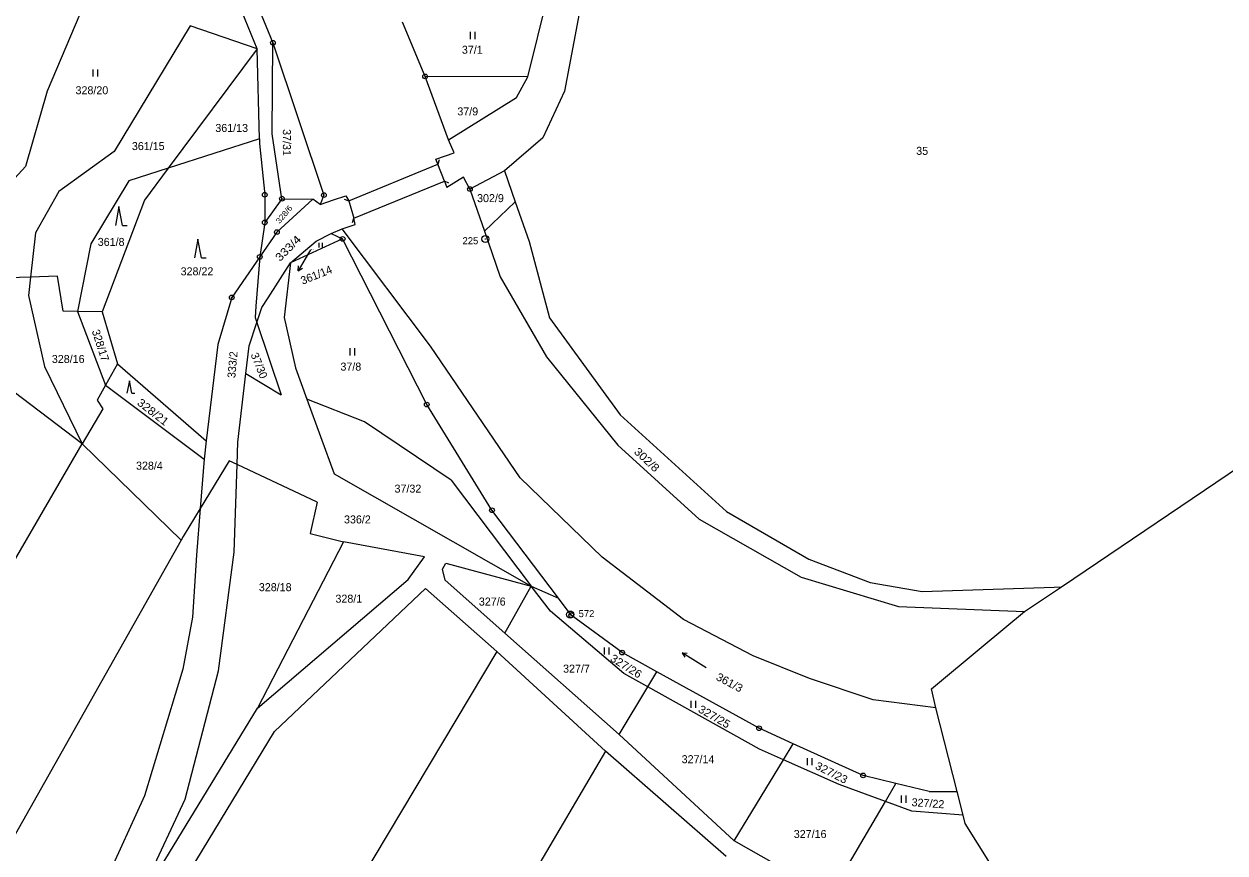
# Model space of a CAD drawing. Extents: x -645290 to -643454, y -1064771 to -1062356.
# Drawn here: x -644666.5 to -644411.4, y -1064149.2 to -1063973.1 of the extents above; entities that cross this region are included whole.
import ezdxf
from ezdxf.enums import TextEntityAlignment as Align

# ---------------------------------------------------------------- set-up
doc = ezdxf.new("R2010")
doc.units = 0
doc.header["$LTSCALE"] = 0.68
for name, color, linetype, lineweight in [('1', 7, 'Continuous', 25), ('3', 7, 'Continuous', 25), ('4', 7, 'Continuous', 13), ('7', 7, 'Continuous', 13), ('8', 7, 'Continuous', 25)]:
    doc.layers.add(name, color=color, linetype=linetype, lineweight=lineweight)
doc.layers.add('2', color=7, linetype='Continuous')

msp = doc.modelspace()

# ---------------------------------------------------------------- linework, layer by layer
at = {"layer": '1'}
for p, q in [((-644621.6, -1063957.55), (-644613.6, -1063977.09)), ((-644616.95, -1063978.39), (-644624.84, -1063958.87)), ((-644559.44, -1063984.36), (-644554.73, -1063965.42)), ((-644547.65, -1063966.35), (-644549.67, -1063976.91)), ((-644654.6, -1063971.04), (-644661.51, -1063987.36)), ((-644581.25, -1063984.25), (-644586.08, -1063972.72)), ((-644631.17, -1063973.52), (-644647.27, -1064000.18)), ((-644616.95, -1063978.39), (-644631.17, -1063973.52)), ((-644613.77, -1063996.44), (-644613.6, -1063977.09)), ((-644613.6, -1063977.09), (-644602.75, -1064009.47)), ((-644549.67, -1063976.91), (-644551.68, -1063987.36)), ((-644616.95, -1063978.39), (-644635.83, -1064003.74)), ((-644616.46, -1063997.53), (-644616.95, -1063978.39)), ((-644559.44, -1063984.36), (-644581.25, -1063984.25)), ((-644576.27, -1063997.73), (-644581.25, -1063984.25)), ((-644561.85, -1063988.75), (-644559.44, -1063984.36)), ((-644661.51, -1063987.36), (-644666.16, -1064003.4)), ((-644551.68, -1063987.36), (-644556.25, -1063997.28)), ((-644576.27, -1063997.73), (-644561.85, -1063988.75)), ((-644616.46, -1063997.53), (-644635.83, -1064003.74)), ((-644616.46, -1063997.53), (-644616.44, -1063998.48)), ((-644616.44, -1063998.48), (-644615.32, -1064009.4)), ((-644611.67, -1064010.23), (-644613.77, -1063996.44)), ((-644575.1, -1064000.47), (-644576.27, -1063997.73)), ((-644556.25, -1063997.28), (-644564.39, -1064004.34)), ((-644647.27, -1064000.18), (-644659.04, -1064008.73)), ((-644578.95, -1064001.85), (-644575.1, -1064000.47)), ((-644666.16, -1064003.4), (-644670.66, -1064008.32)), ((-644578.53, -1064002.93), (-644578.95, -1064001.85)), ((-644577.14, -1064006.51), (-644578.53, -1064002.93)), ((-644635.83, -1064003.74), (-644644.19, -1064006.42)), ((-644635.83, -1064003.74), (-644640.87, -1064010.51)), ((-644573.1, -1064005.65), (-644576.62, -1064007.88)), ((-644571.73, -1064008.18), (-644573.1, -1064005.65)), ((-644564.39, -1064004.34), (-644571.73, -1064008.18)), ((-644564.39, -1064004.34), (-644562.1, -1064010.87)), ((-644659.04, -1064008.73), (-644664.02, -1064017.46)), ((-644644.19, -1064006.42), (-644652.29, -1064019.8)), ((-644577.14, -1064006.51), (-644576.62, -1064007.88)), ((-644571.73, -1064008.18), (-644568.65, -1064017.15)), ((-644640.87, -1064010.51), (-644649.88, -1064034.3)), ((-644615.32, -1064009.4), (-644615.32, -1064015.29)), ((-644611.67, -1064010.23), (-644615.32, -1064015.29)), ((-644605.13, -1064010.36), (-644612.74, -1064017.34)), ((-644611.67, -1064010.23), (-644605.13, -1064010.36)), ((-644603.57, -1064011.46), (-644605.13, -1064010.36)), ((-644602.75, -1064009.47), (-644603.57, -1064011.46)), ((-644603.57, -1064011.46), (-644600.73, -1064010.49)), ((-644600.73, -1064010.49), (-644598.11, -1064009.61)), ((-644598.11, -1064009.61), (-644597.49, -1064010.68)), ((-644597.49, -1064010.68), (-644596.38, -1064014.34)), ((-644568.65, -1064017.15), (-644562.1, -1064010.87)), ((-644562.1, -1064010.87), (-644559.12, -1064019.33)), ((-644615.32, -1064015.29), (-644616.37, -1064022.59)), ((-644598.85, -1064016.67), (-644596.09, -1064015.71)), ((-644596.09, -1064015.71), (-644596.38, -1064014.34)), ((-644664.02, -1064017.46), (-644665.04, -1064026.88)), ((-644612.74, -1064017.34), (-644616.37, -1064022.59)), ((-644598.77, -1064018.77), (-644609.82, -1064023.89)), ((-644604.43, -1064019.27), (-644601.19, -1064017.65)), ((-644601.19, -1064017.65), (-644598.85, -1064016.67)), ((-644601.19, -1064017.65), (-644598.77, -1064018.77)), ((-644580.13, -1064041.56), (-644598.85, -1064016.67)), ((-644580.91, -1064053.97), (-644598.77, -1064018.77)), ((-644568.65, -1064017.15), (-644565.32, -1064026.84)), ((-644652.29, -1064019.8), (-644655.11, -1064034.23)), ((-644609.82, -1064023.89), (-644604.43, -1064019.27)), ((-644559.12, -1064019.33), (-644554.82, -1064035.56)), ((-644616.37, -1064022.59), (-644622.34, -1064031.2)), ((-644616.37, -1064022.59), (-644617.19, -1064033.09)), ((-644614.59, -1064031.29), (-644609.82, -1064023.89)), ((-644609.82, -1064023.89), (-644611.22, -1064035.44)), ((-644665.04, -1064026.88), (-644672.56, -1064027.12)), ((-644665.04, -1064026.88), (-644665.47, -1064030.8)), ((-644659.34, -1064026.7), (-644665.04, -1064026.88)), ((-644658.14, -1064034.16), (-644659.34, -1064026.7)), ((-644565.32, -1064026.84), (-644555.5, -1064043.84)), ((-644665.47, -1064030.8), (-644662.12, -1064045.9)), ((-644622.34, -1064031.2), (-644625.31, -1064041.18)), ((-644615.92, -1064033.36), (-644614.59, -1064031.29)), ((-644655.11, -1064034.23), (-644658.14, -1064034.16)), ((-644649.88, -1064034.3), (-644655.11, -1064034.23)), ((-644655.11, -1064034.23), (-644649.11, -1064049.86)), ((-644617.19, -1064033.09), (-644617.34, -1064035.5)), ((-644616.99, -1064036.55), (-644615.92, -1064033.36)), ((-644649.88, -1064034.3), (-644646.58, -1064045.29)), ((-644618.64, -1064041.47), (-644616.99, -1064036.55)), ((-644617.34, -1064035.5), (-644616.99, -1064036.55)), ((-644616.99, -1064036.55), (-644611.82, -1064051.92)), ((-644554.82, -1064035.56), (-644539.85, -1064056.15)), ((-644625.31, -1064041.18), (-644627.74, -1064061.65)), ((-644619.32, -1064047.34), (-644618.64, -1064041.47)), ((-644561.08, -1064069.56), (-644580.13, -1064041.56)), ((-644654.09, -1064062.28), (-644680.91, -1064041.96)), ((-644555.5, -1064043.84), (-644540.34, -1064062.59)), ((-644662.12, -1064045.9), (-644654.09, -1064062.28)), ((-644646.58, -1064045.29), (-644649.11, -1064049.86)), ((-644646.58, -1064045.29), (-644627.74, -1064061.65)), ((-644621.03, -1064061.97), (-644619.32, -1064047.34)), ((-644619.32, -1064047.34), (-644611.82, -1064051.92)), ((-644649.11, -1064049.86), (-644650.93, -1064053.03)), ((-644649.11, -1064049.86), (-644628.21, -1064065.59)), ((-644650.93, -1064053.03), (-644649.73, -1064054.86)), ((-644606.37, -1064052.81), (-644600.56, -1064068.66)), ((-644594.12, -1064057.65), (-644606.37, -1064052.81)), ((-644567.05, -1064076.43), (-644580.91, -1064053.97)), ((-644446.09, -1064092.67), (-644389.56, -1064054.44)), ((-644649.73, -1064054.86), (-644654.09, -1064062.28)), ((-644517.23, -1064076.68), (-644539.85, -1064056.15)), ((-644575.75, -1064070), (-644594.12, -1064057.65)), ((-644794.48, -1064303.81), (-644654.09, -1064062.28)), ((-644633.09, -1064082.79), (-644654.09, -1064062.28)), ((-644627.74, -1064061.65), (-644628.21, -1064065.59)), ((-644621.19, -1064066.68), (-644621.03, -1064061.97)), ((-644540.34, -1064062.59), (-644523.03, -1064078.34)), ((-644628.21, -1064065.59), (-644629.05, -1064076.08)), ((-644622.86, -1064065.89), (-644629.05, -1064076.08)), ((-644621.19, -1064066.68), (-644622.86, -1064065.89)), ((-644621.81, -1064085.36), (-644621.19, -1064066.68)), ((-644604.16, -1064074.72), (-644621.19, -1064066.68)), ((-644600.56, -1064068.66), (-644558.7, -1064092.57)), ((-644543.64, -1064086.36), (-644561.08, -1064069.56)), ((-644575.75, -1064070), (-644558.7, -1064092.57)), ((-644604.16, -1064074.72), (-644605.66, -1064081.34)), ((-644629.05, -1064076.08), (-644632.63, -1064081.97)), ((-644629.05, -1064076.08), (-644629.84, -1064085.97)), ((-644552.95, -1064095.09), (-644567.05, -1064076.43)), ((-644517.23, -1064076.68), (-644499.75, -1064086.83)), ((-644523.03, -1064078.34), (-644501.38, -1064090.61)), ((-644632.63, -1064081.97), (-644633.09, -1064082.79)), ((-644605.66, -1064081.34), (-644598.6, -1064083.1)), ((-644633.09, -1064082.79), (-644728.84, -1064252.56)), ((-644598.6, -1064083.1), (-644616.86, -1064118.44)), ((-644581.42, -1064086.34), (-644598.6, -1064083.1)), ((-644629.84, -1064085.97), (-644630.64, -1064099.14)), ((-644625.15, -1064110.54), (-644621.81, -1064085.36)), ((-644584.88, -1064091.13), (-644581.42, -1064086.34)), ((-644577.53, -1064088.92), (-644576.86, -1064087.65)), ((-644576.86, -1064087.65), (-644558.7, -1064092.57)), ((-644526.35, -1064099.66), (-644543.64, -1064086.36)), ((-644499.75, -1064086.83), (-644486.74, -1064091.8)), ((-644576.99, -1064091.31), (-644577.53, -1064088.92)), ((-644616.86, -1064118.44), (-644584.88, -1064091.13)), ((-644564.35, -1064102.54), (-644576.99, -1064091.31)), ((-644564.35, -1064102.54), (-644558.7, -1064092.57)), ((-644558.7, -1064092.57), (-644552.95, -1064095.09)), ((-644554.6, -1064097.87), (-644558.7, -1064092.57)), ((-644501.38, -1064090.61), (-644480.67, -1064096.9)), ((-644486.74, -1064091.8), (-644475.7, -1064093.7)), ((-644475.7, -1064093.7), (-644447.66, -1064092.77)), ((-644453.91, -1064097.96), (-644446.09, -1064092.67)), ((-644447.66, -1064092.77), (-644446.09, -1064092.67)), ((-644613.22, -1064123.4), (-644581.18, -1064093.06)), ((-644581.18, -1064093.06), (-644566.05, -1064106.42)), ((-644550.22, -1064098.7), (-644552.95, -1064095.09)), ((-644539.08, -1064111.13), (-644554.6, -1064097.87)), ((-644480.67, -1064096.9), (-644453.91, -1064097.96)), ((-644462.7, -1064105.25), (-644453.91, -1064097.96)), ((-644630.64, -1064099.14), (-644632.7, -1064110.17)), ((-644539.41, -1064106.66), (-644550.22, -1064098.7)), ((-644511.55, -1064107.35), (-644526.35, -1064099.66)), ((-644540.03, -1064124.08), (-644564.35, -1064102.54)), ((-644473.67, -1064114.35), (-644462.7, -1064105.25)), ((-644566.05, -1064106.42), (-644726.5, -1064375.38)), ((-644542.91, -1064127.64), (-644566.05, -1064106.42)), ((-644532.03, -1064110.74), (-644539.41, -1064106.66)), ((-644499.61, -1064112.14), (-644511.55, -1064107.35)), ((-644632.7, -1064110.17), (-644640.85, -1064137.12)), ((-644632.24, -1064137.78), (-644625.15, -1064110.54)), ((-644533.97, -1064113.97), (-644532.03, -1064110.74)), ((-644510.32, -1064122.73), (-644532.03, -1064110.74)), ((-644533.97, -1064113.97), (-644539.08, -1064111.13)), ((-644486.07, -1064116.73), (-644499.61, -1064112.14)), ((-644540.03, -1064124.08), (-644533.97, -1064113.97)), ((-644510.23, -1064127.16), (-644533.97, -1064113.97)), ((-644472.76, -1064118.41), (-644473.67, -1064114.35)), ((-644643.64, -1064162.33), (-644616.86, -1064118.44)), ((-644472.76, -1064118.41), (-644486.07, -1064116.73)), ((-644468.24, -1064136.2), (-644472.76, -1064118.41)), ((-644711.6, -1064285.03), (-644613.22, -1064123.4)), ((-644503.08, -1064126.02), (-644510.32, -1064122.73)), ((-644515.6, -1064146.63), (-644540.03, -1064124.08)), ((-644505.15, -1064129.43), (-644503.08, -1064126.02)), ((-644488.22, -1064132.77), (-644503.08, -1064126.02)), ((-644542.91, -1064127.64), (-644679.8, -1064359.5)), ((-644517.28, -1064150.01), (-644542.91, -1064127.64)), ((-644505.15, -1064129.43), (-644510.23, -1064127.16)), ((-644515.6, -1064146.63), (-644505.15, -1064129.43)), ((-644493.31, -1064134.72), (-644505.15, -1064129.43)), ((-644481.26, -1064134.46), (-644488.22, -1064132.77)), ((-644483.49, -1064138.28), (-644493.31, -1064134.72)), ((-644483.49, -1064138.28), (-644481.26, -1064134.46)), ((-644474.2, -1064136.18), (-644481.26, -1064134.46)), ((-644474.2, -1064136.18), (-644468.24, -1064136.2)), ((-644466.97, -1064141.18), (-644468.24, -1064136.2)), ((-644640.85, -1064137.12), (-644651.74, -1064160.97)), ((-644643.64, -1064162.33), (-644632.24, -1064137.78)), ((-644495.15, -1064158.24), (-644483.49, -1064138.28)), ((-644477.85, -1064140.32), (-644483.49, -1064138.28)), ((-644466.97, -1064141.18), (-644477.85, -1064140.32)), ((-644466.54, -1064142.99), (-644466.97, -1064141.18)), ((-644456.36, -1064159.09), (-644466.54, -1064142.99)), ((-644495.15, -1064158.24), (-644515.6, -1064146.63))]:
    msp.add_line(p, q, dxfattribs=at)
msp.add_lwpolyline([(-644611.22, -1064035.44), (-644608.82, -1064046.14), (-644606.37, -1064052.81)], dxfattribs=at)
at = {"layer": '3'}
for p, q in [((-644571.641, -1063976.31), (-644571.641, -1063974.81)), ((-644570.64, -1063976.31), (-644570.64, -1063974.81)), ((-644651.791, -1063984.28), (-644651.791, -1063982.78)), ((-644650.79, -1063984.28), (-644650.79, -1063982.78)), ((-644645.54, -1064015.9), (-644644.544, -1064015.9)), ((-644603.732, -1064020.61), (-644603.732, -1064019.605)), ((-644603.062, -1064020.61), (-644603.062, -1064019.605)), ((-644628.75, -1064022.8), (-644627.754, -1064022.8)), ((-644597.181, -1064043.52), (-644597.181, -1064042.02)), ((-644596.18, -1064043.52), (-644596.18, -1064042.02)), ((-644643.578, -1064051.58), (-644642.91, -1064051.58)), ((-644543.131, -1064107.09), (-644543.131, -1064105.59)), ((-644542.13, -1064107.09), (-644542.13, -1064105.59)), ((-644526.674, -1064106.694), (-644525.58, -1064106.786)), ((-644524.721, -1064118.42), (-644524.721, -1064116.92)), ((-644523.72, -1064118.42), (-644523.72, -1064116.92)), ((-644500.061, -1064130.59), (-644500.061, -1064129.09)), ((-644499.06, -1064130.59), (-644499.06, -1064129.09)), ((-644480.091, -1064138.56), (-644480.091, -1064137.06)), ((-644479.09, -1064138.56), (-644479.09, -1064137.06))]:
    msp.add_line(p, q, dxfattribs=at)
for points in [[(-644645.54, -1064015.9), (-644646.29, -1064011.9), (-644647.04, -1064015.9)], [(-644628.75, -1064022.8), (-644629.5, -1064018.8), (-644630.25, -1064022.8)], [(-644643.578, -1064051.58), (-644644.08, -1064048.9), (-644644.582, -1064051.58)], [(-644521.586, -1064109.873), (-644526.674, -1064106.694), (-644526.111, -1064107.637)]]:
    msp.add_lwpolyline(points, dxfattribs=at)
at = {"layer": '4'}
for p, q in [((-644597.49, -1064010.68), (-644578.53, -1064002.93)), ((-644578.237, -1064001.973), (-644578.529, -1064002.93)), ((-644596.38, -1064014.34), (-644577.14, -1064006.51)), ((-644576.249, -1064006.965), (-644577.14, -1064006.511)), ((-644598.417, -1064010.305), (-644597.49, -1064010.679)), ((-644596.69, -1064015.291), (-644596.381, -1064014.34))]:
    msp.add_line(p, q, dxfattribs=at)
at = {"layer": '7'}
msp.add_line((-644608.2, -1064025.579), (-644607.266, -1064024.962), dxfattribs=at)
msp.add_lwpolyline([(-644605.59, -1064021.09), (-644606.7, -1064022.98), (-644608.2, -1064025.579), (-644608.133, -1064024.461)], dxfattribs=at)
at = {"layer": '8'}
for centre, radius in [((-644613.6, -1063977.0899), 0.5), ((-644613.6, -1063977.0899), 0.0303), ((-644581.25, -1063984.2499), 0.5), ((-644581.25, -1063984.2499), 0.0303), ((-644571.73, -1064008.1799), 0.5), ((-644571.73, -1064008.1799), 0.0303), ((-644615.32, -1064009.3999), 0.5), ((-644615.32, -1064009.3999), 0.0303), ((-644611.67, -1064010.2299), 0.5), ((-644611.67, -1064010.2299), 0.0303), ((-644602.75, -1064009.4699), 0.5), ((-644602.75, -1064009.4699), 0.0303), ((-644615.32, -1064015.2899), 0.5), ((-644615.32, -1064015.2899), 0.0303), ((-644612.74, -1064017.3399), 0.5), ((-644612.74, -1064017.3399), 0.0303), ((-644598.77, -1064018.7699), 0.5), ((-644598.77, -1064018.7699), 0.0303), ((-644568.46, -1064018.7898), 0.75), ((-644568.46, -1064018.7898), 0.03), ((-644616.37, -1064022.5899), 0.5), ((-644616.37, -1064022.5899), 0.0303), ((-644622.34, -1064031.1999), 0.5), ((-644622.34, -1064031.1999), 0.0303), ((-644580.91, -1064053.9699), 0.5), ((-644580.91, -1064053.9699), 0.0303), ((-644567.05, -1064076.4299), 0.5), ((-644567.05, -1064076.4299), 0.0303), ((-644550.44, -1064098.5798), 0.75), ((-644550.22, -1064098.6999), 0.5), ((-644550.44, -1064098.5798), 0.03), ((-644550.22, -1064098.6999), 0.0303), ((-644539.41, -1064106.6599), 0.5), ((-644539.41, -1064106.6599), 0.0303), ((-644510.32, -1064122.7299), 0.5), ((-644510.32, -1064122.7299), 0.0303), ((-644488.22, -1064132.7699), 0.5), ((-644488.22, -1064132.7699), 0.0303)]:
    msp.add_circle(centre, radius, dxfattribs=at)

# ---------------------------------------------------------------- texts
at = {"layer": '2'}
for s, p in [('37/1', (-644571.229, -1063979.435)), ('37/9', (-644572.199, -1063992.535))]:
    msp.add_text(s, height=1.7, dxfattribs=at).set_placement(p, align=Align.CENTER)
for s, height, p in [('328/20', 1.7, (-644655.51, -1063988.045)), ('361/13', 1.7, (-644625.82, -1063996.054)), ('361/15', 1.7, (-644643.54, -1063999.905)), ('35', 1.7, (-644476.94, -1064000.915)), ('302/9', 1.7, (-644570.22, -1064010.965)), ('361/8', 1.7, (-644650.79, -1064020.265)), ('361/14', 0.2, (-644605.59, -1064021.14)), ('328/22', 1.7, (-644633.19, -1064026.515)), ('328/16', 1.7, (-644660.54, -1064045.135)), ('37/8', 1.7, (-644599.24, -1064046.755)), ('328/4', 1.7, (-644642.66, -1064067.804)), ('37/32', 1.7, (-644587.75, -1064072.675)), ('336/2', 1.7, (-644598.48, -1064079.225)), ('328/18', 1.7, (-644616.57, -1064093.615)), ('328/1', 1.7, (-644600.3, -1064096.064)), ('327/6', 1.7, (-644569.84, -1064096.675)), ('327/7', 1.7, (-644551.95, -1064110.925)), ('327/14', 1.7, (-644526.76, -1064130.165)), ('327/16', 1.7, (-644502.95, -1064146.054))]:
    msp.add_text(s, height=height, dxfattribs=at).set_placement(p)
for s, rotation, p in [('37/31', 270, (-644611.465, -1063995.45)), ('328/17', 288, (-644652.074, -1064038.361)), ('333/2', 85, (-644621.576, -1064048.407)), ('37/30', 292, (-644618.354, -1064043.359)), ('327/22', 356, (-644477.969, -1064139.273))]:
    msp.add_text(s, height=1.7, rotation=rotation, dxfattribs=at).set_placement(p)
for s, height, rotation, width, p in [('328/6', 1.2, 50, 1.1, (-644612.16, -1064015.642)), ('333/4', 1.7, 45, 1.15, (-644612.079, -1064023.68)), ('328/21', 1.7, 322, 1.1, (-644642.581, -1064053.874)), ('302/8', 1.7, 317, 1.1, (-644537.029, -1064064.18)), ('327/26', 1.7, 328, 1.05, (-644542.095, -1064108.34)), ('327/25', 1.7, 330, 1.05, (-644523.402, -1064119.188)), ('327/23', 1.7, 333, 1.05, (-644498.572, -1064131.278))]:
    msp.add_text(s, height=height, rotation=rotation, dxfattribs=dict(at, width=width)).set_placement(p)
msp.add_text('361/14', height=1.7, rotation=22, dxfattribs=at).set_placement((-644600.8238, -1064025.9269), align=Align.RIGHT)
at = {"layer": '2', "width": 1.05}
msp.add_text('361/3', height=1.7, rotation=332, dxfattribs=at).set_placement((-644516.9856, -1064113.7726), align=Align.CENTER)
at = {"layer": '8'}
msp.add_text('225', height=1.5, dxfattribs=at).set_placement((-644569.959, -1064019.907), align=Align.RIGHT)
msp.add_text('572', height=1.5, dxfattribs=at).set_placement((-644548.65, -1064099.135))

doc.saveas('drawing.dxf')
